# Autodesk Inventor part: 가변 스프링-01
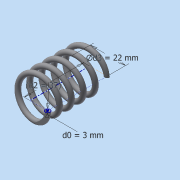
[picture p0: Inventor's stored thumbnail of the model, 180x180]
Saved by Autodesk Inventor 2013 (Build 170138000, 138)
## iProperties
Created: 2014-12
Part Number: 가변 스프링-01
Material: 강철, 탄소
Document SubType Name: Modeling
Designer: WINDOWS7
Density: 7.87 g/cm^3
Mass: 18.8927 g
Surface Area: 32.5299 cm^2
Volume: 2.40059 cm^3
Author: WINDOWS7
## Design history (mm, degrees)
sketch "스케치1"
  geometry: L1 (0, 0)-(11, 0); L2 (11, 0)-(11, 36.411); L3 (11, 36.411)-(0, 36.411); L4 (0, 36.411)-(0, 0); C1 r 1.5 at (11, 0)
  constraints: 8 end point, 2 parallel, 1 centre point, 1 coincident, 1 horizontal, 1 perpendicular
  dimensions: "d0" = 3 diameter of C1; "d2" = 36.4112 distance of L3.end L1.start (derived); "d3" = 22 diameter of L2 L4
feature "코일1" pitch "d4" = 10; turns "d6" = 5; dims "d5" = 36.4112 (= d2), "d7" = 0, angle "d8" = 90 deg, angle "d9" = 90 deg, "d10" = 0, "d11" = 0
node "작업 평면1"
sketch "스케치2"
  geometry: L1 (-12.5, 0)-(-9.5, 0) reference; 1 further point
  constraints: 1 horizontal alignment
extrude "돌출1" cut sketch "스케치2" distance "d13" = 10; taper "d14" = 0 deg
node "작업 평면2"
sketch "스케치3"
  geometry: L1 (-9.5, 0)-(-12.5, 0) reference; 1 further point
  constraints: 1 horizontal alignment
extrude "돌출2" cut sketch "스케치3" distance "d16" = 10; taper "d17" = 0 deg
node "솔리드1"
node "절단 모서리 투영1"
node "절단 모서리 투영2"
other parameters: "d12" = 0, "d15" = 36.4112 (= d2)
